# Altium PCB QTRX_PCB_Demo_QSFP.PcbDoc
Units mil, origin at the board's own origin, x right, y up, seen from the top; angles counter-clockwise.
Board outline 1267.75 x 649.64 mil, 6 copper layers (Top Layer, GND1, VCC(2V5), signal_VCC1V2, GND2, Bottom Layer), stack 37.5 mil thick; 33 components, 47 nets, 149 pads, 50 vias.
Unrouted connection lines stored in the file: 63.
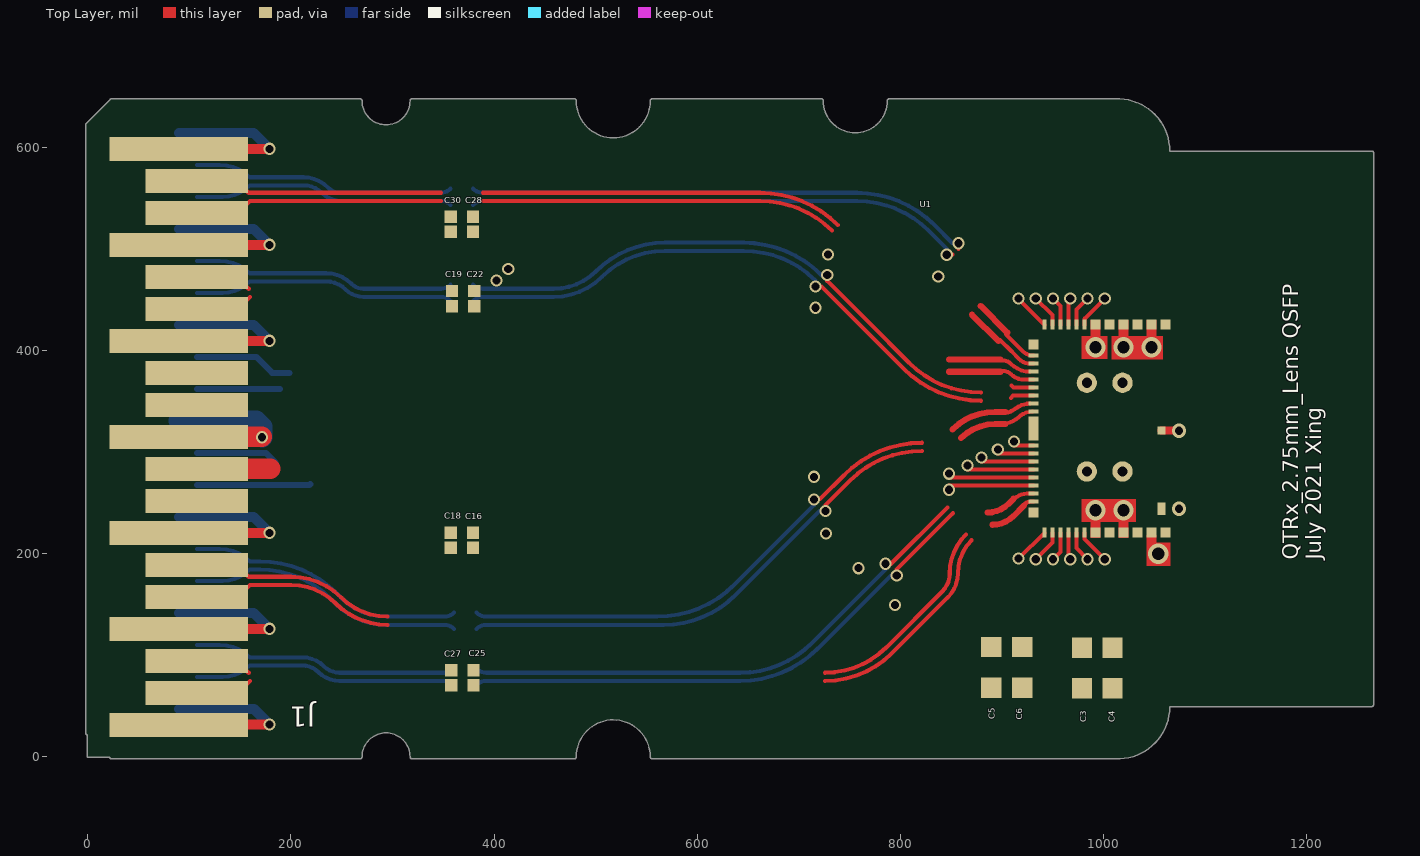
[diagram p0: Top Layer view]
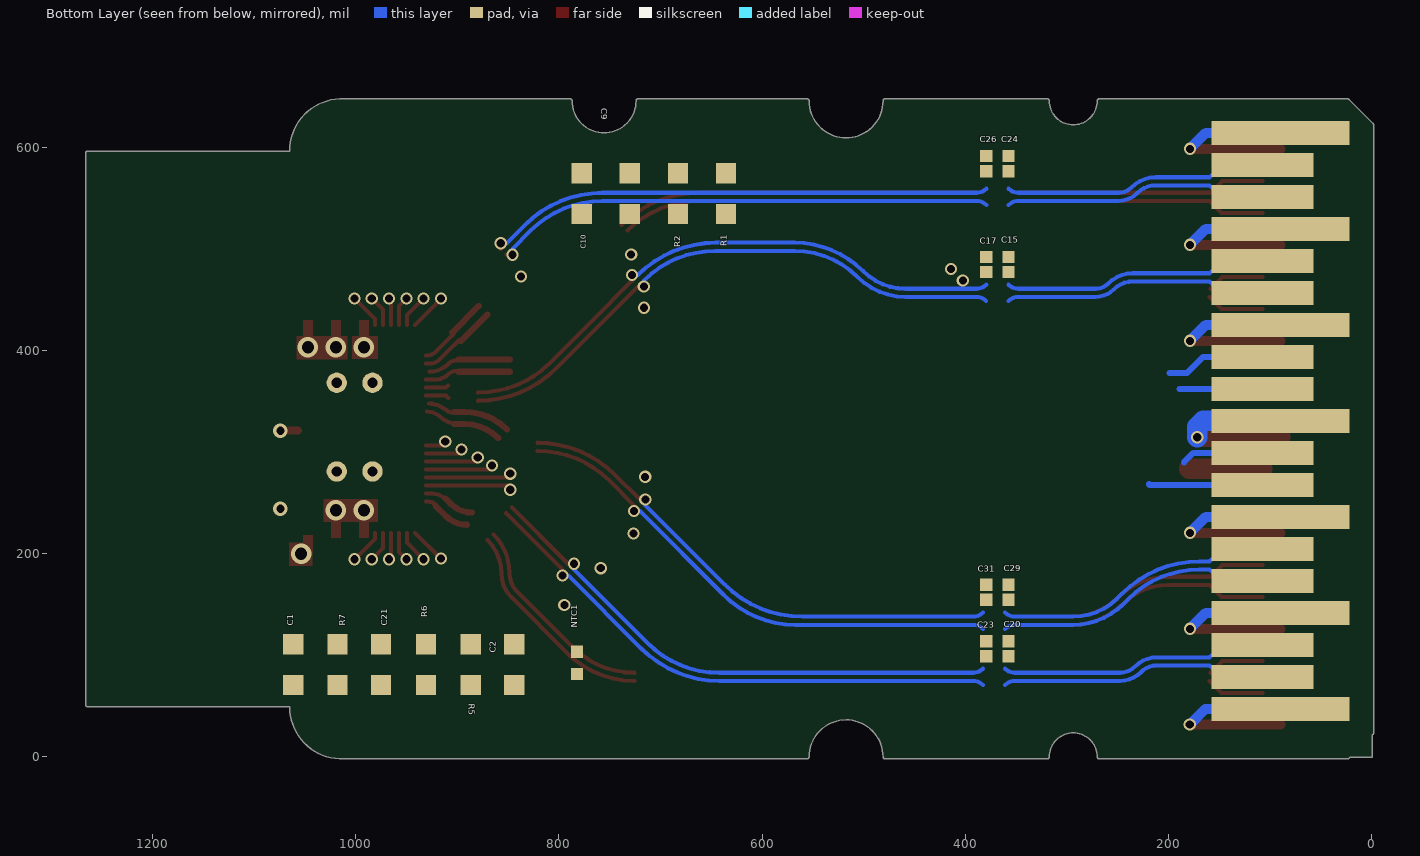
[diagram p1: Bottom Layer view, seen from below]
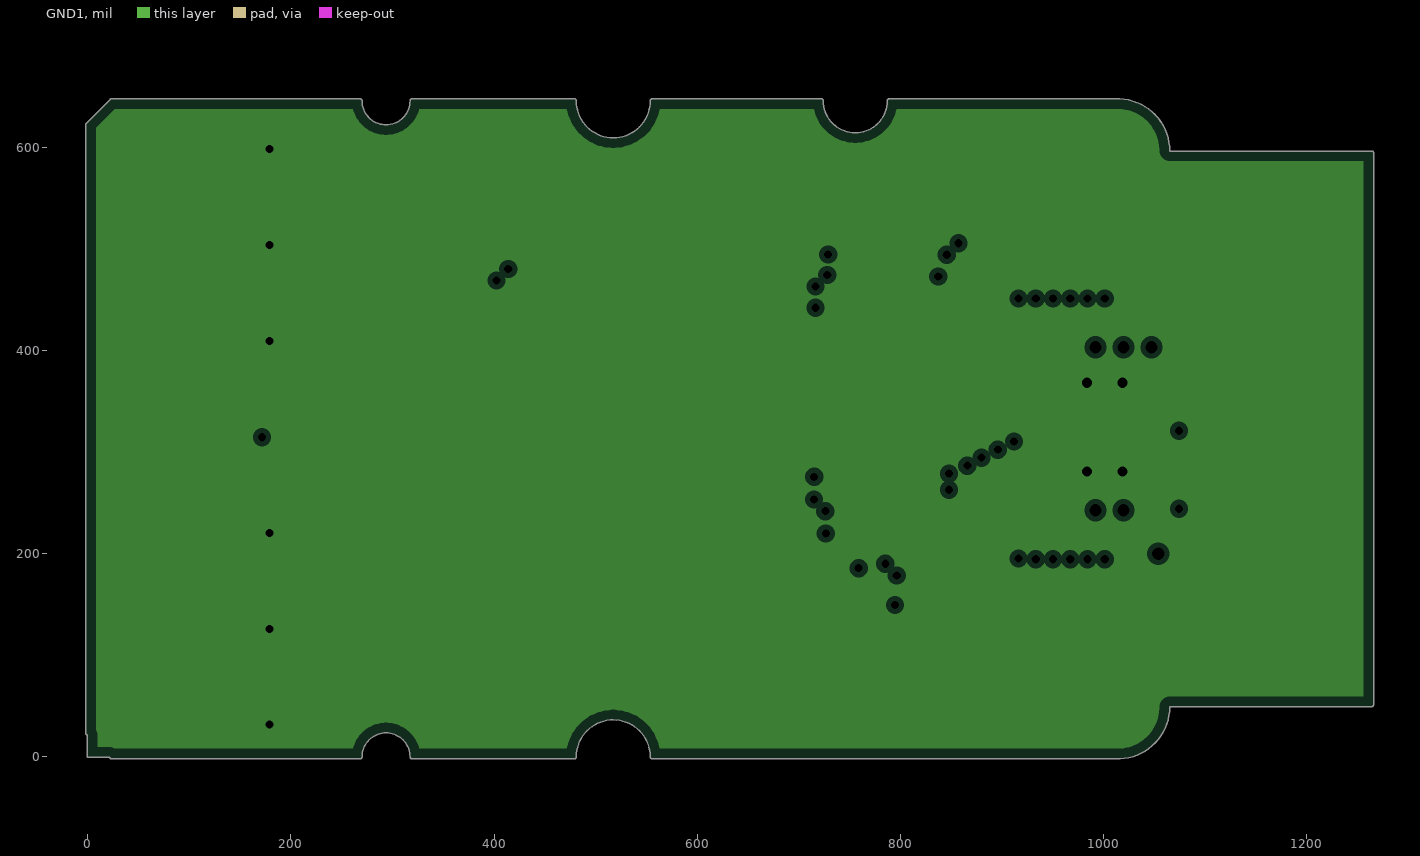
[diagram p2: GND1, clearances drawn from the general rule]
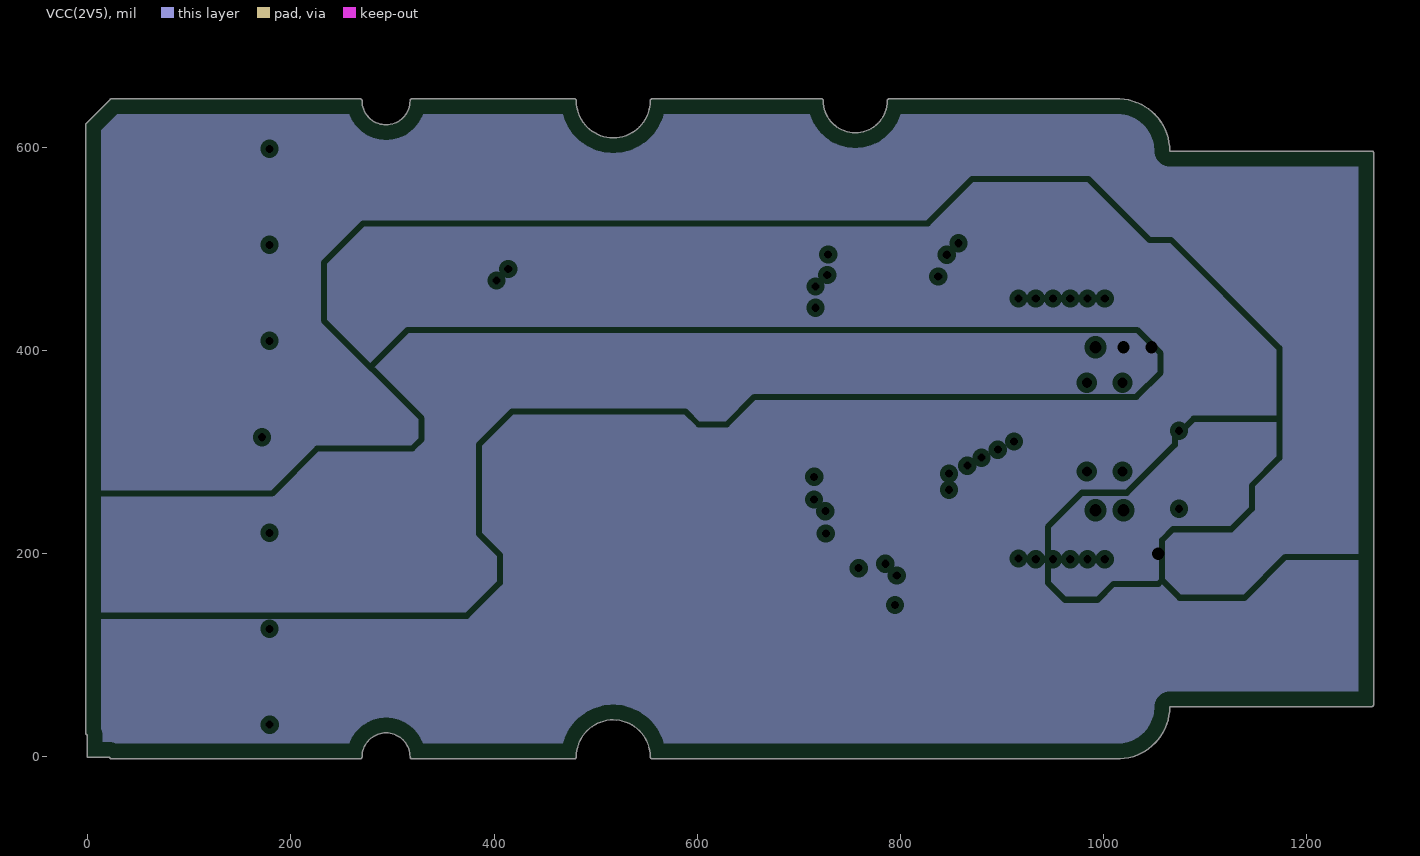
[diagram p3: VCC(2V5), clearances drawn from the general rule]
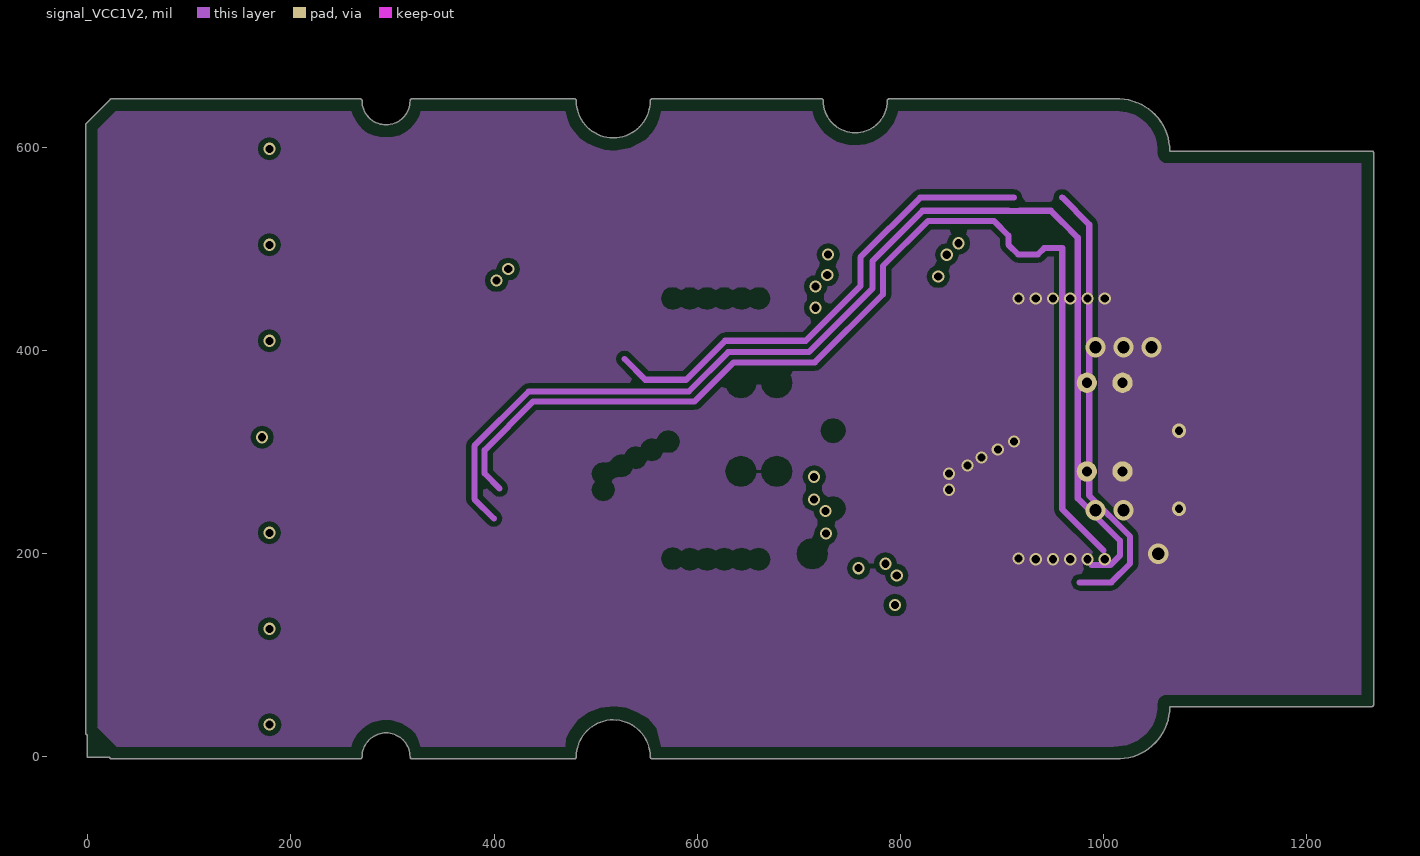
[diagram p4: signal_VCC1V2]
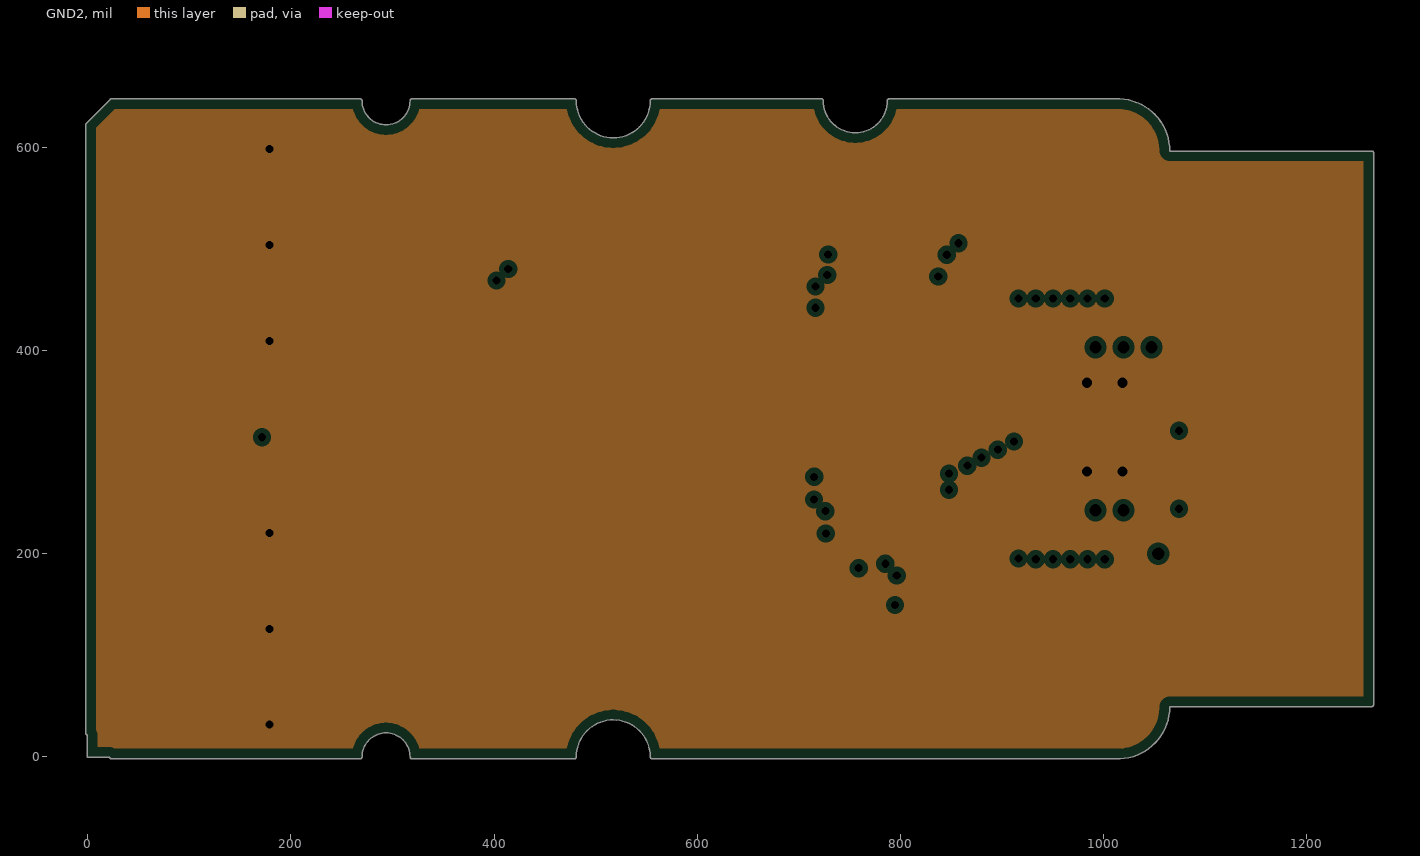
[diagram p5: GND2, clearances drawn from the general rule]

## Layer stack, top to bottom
Top Solder: solder mask 0.7, Solder Resist, Dk 3.5
Top Layer: signal copper 1.65
Dielectric 1: core 4, CORE NPG 186, Dk 4.6
GND1: plane copper 0.6, net GND
Dielectric 2: prepreg 8.3, PREPREG 7628HR, Dk 4.1
VCC(2V5): plane copper 1.2, net VCC2V5
Dielectric 3: dielectric 6, FR-4, Dk 4.8
signal_VCC1V2: signal copper 1.2
Dielectric 4: prepreg 8.3, PREPREG 7628HR, Dk 4.1
GND2: plane copper 0.6, net GND
Dielectric 5: core 4, CORE NPG 186, Dk 4.6
Bottom Layer: signal copper 1.65
Bottom Solder: solder mask 0.7, Solder Resist, Dk 3.5

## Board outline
0,-0.41 21.23,-0.41 22.22,-1.4 22.2,-1.39 ccw(c23.62,0) 23.62,-1.98 267.98,-1.98 ccw(c268.11,0) 270.08,-0.19 ccw(c268.11,0) 270.09,0 ccw(c268.11,0) 270.09,0.04 cw(c293.7,0) 317.31,0 cw(c293.7,0) 317.31,0 ccw(c319.29,0) 319.39,-1.98 478.81,-1.98 ccw(c478.94,0) 480.91,-0.19 ccw(c478.94,0) 480.92,0 ccw(c478.94,0) 480.92,0.04 cw(c517.32,0) 553.73,0 ccw(c555.71,0) 555.71,-1.99 1015.75,-1.99 ccw(c1015.75,0) 1015.96,-1.98 ccw(c1013.68,49.31) 1065.02,49.31 ccw(c1013.68,49.31) 1065.02,49.39 1263.78,49.39 ccw(c1263.78,51.38) 1265.76,51.38 1265.76,594.29 ccw(c1263.78,594.29) 1263.78,596.27 1065.02,596.27 ccw(c1013.68,596.36) 1065.02,596.36 ccw(c1013.68,596.36) 1015.83,647.65 ccw(c1015.75,645.67) 1015.75,647.65 788.98,647.65 ccw(c788.98,645.67) 786.99,645.67 cw(c755.51,645.67) 724.03,645.63 ccw(c722.05,645.67) 724.03,645.67 ccw(c722.05,645.67) 724.02,645.86 ccw(c722.05,645.67) 721.92,647.65 555.78,647.65 ccw(c555.71,645.67) 553.73,645.67 cw(c517.32,645.67) 553.73,645.67 cw(c517.32,645.67) 480.92,645.63 cw(c517.32,645.67) 480.92,645.67 ccw(c478.94,645.67) 480.91,645.86 ccw(c478.94,645.67) 478.81,647.65 319.39,647.65 ccw(c319.29,645.67) 317.31,645.67 cw(c293.7,645.67) 317.31,645.67 cw(c293.7,645.67) 270.09,645.63 cw(c293.7,645.67) 270.09,645.67 ccw(c268.11,645.67) 270.08,645.86 ccw(c268.11,645.67) 267.98,647.65 23.62,647.65 ccw(c23.62,645.67) 22.21,647.06 22.22,647.07 -1.4,623.45 -1.39,623.46 ccw(c0,622.04) -1.98,622.04 -1.98,23.62 ccw(c0,23.62) -1.39,22.21 -1.4,22.22 -0.41,21.23 -0.41,0 ccw(c0,0)

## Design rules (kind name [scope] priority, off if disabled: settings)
Clearance Clearance_1 [InPolygon and InNet('GND') vs InAnyDifferentialPair] p1: gap=10 ignorepadtopadclearanceinfootprint=TRUE
Clearance Clearance_2 [InPolygon and InNet('GND') vs InNet('DIS') or InNet('RSTN') or InNet('SCL') or InNet('SDA') or InNet('A5_1') or InNet('A5_2') or InNet('A6_1') or InNet('A6_2')] p2: gap=5.2 ignorepadtopadclearanceinfootprint=TRUE
Clearance [All] p3: gap=5 ignorepadtopadclearanceinfootprint=TRUE
DiffPairsRouting [All] p1: maxlimit=7 minlimit=7 mostfreqgap=7 toplayer_minwidth=5 toplayer_maxwidth=5 toplayer_prefwidth=5 midlayer1_minwidth=5 midlayer1_maxwidth=5 midlayer1_prefwidth=5 bottomlayer_minwidth=5 bottomlayer_maxwidth=5 bottomlayer_prefwidth=5 maxuncoupledlength=500
HoleSize [All] p1: absolutevalues=TRUE maxlimit=120 minlimit=1 maxpercent=80.000 minpercent=20.000
HoleToHoleClearance [All] p1: gap=5 allowstackedmicrovias=TRUE
PlaneClearance [All] p1: clearance=5
PlaneConnect [All] p1: planeconnectstyle=Direct reliefexpansion=30 reliefentries=4 reliefconductorwidth=30 reliefairgap=5
PolygonConnect [All] p1: connectstyle=Direct reliefconductorwidth=10 reliefentries=4 polygonreliefangle="90 Angle" airgapwidth=10
RoutingVias [All] p1: holewidth=28 width=50 viastyle="Through Hole" minholewidth=28 minwidth=50 maxholewidth=28 maxwidth=50
SilkToSilkClearance [All] p1: silktosilkclearance=5
SilkToSolderMaskClearance [IsPad] p1: minsilkscreentomaskgap=5 clearancetoexposedcopper=TRUE
SolderMaskExpansion [All] p1: expansion=4 istentingtop=FALSE
Width [All] p1: maxlimit=5 minlimit=5 preferedwidth=5
23 further rules are at their usual default settings.

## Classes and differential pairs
differential pair RX4: +RX4_p -RX4_n
differential pair RX3: +RX3_p -RX3_n
differential pair RX2: +RX2_p -RX2_n
differential pair TX4: +TX4_p -TX4_n
differential pair TX3: +TX3_p -TX3_n
differential pair TX2: +TX2_p -TX2_n
differential pair TX1: +TX1_p -TX1_n
differential pair RX1: +RX1_p -RX1_n
differential pair TXc4: +TXc4_p -TXc4_n
differential pair TXc3: +TXc3_p -TXc3_n
differential pair TXc2: +TXc2_p -TXc2_n
differential pair TXc1: +TXc1_p -TXc1_n
differential pair RXc4: +RXc4_p -RXc4_n
differential pair RXc3: +RXc3_p -RXc3_n
differential pair RXc2: +RXc2_p -RXc2_n
differential pair RXc1: +RXc1_p -RXc1_n

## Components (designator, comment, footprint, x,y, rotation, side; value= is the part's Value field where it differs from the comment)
C1 "Cap 0.1uF" 0402-eagle 1061.27,110.73 r270 bottom value=0.1uF
C2 "Cap 1nF" 0402-eagle 843.98,110.73 r270 bottom value=1nF
C3 "Cap 0.1uF" 0402-eagle 978.71,67.46 r90 top value=0.1uF
C4 "Cap 1nF" 0402-eagle 1008.71,67.46 r90 top value=1nF
C5 "Cap 0.1uF" 0402-eagle 889.41,68.03 r90 top value=0.1uF
C6 "Cap 1nF" 0402-eagle 919.8,68.03 r90 top value=1nF
C9 "Cap 0.1uF" 0402-eagle 730.14,534.36 r90 bottom value=0.1uF
C10 "Cap 1nF" 0402-eagle 777.47,534.36 r90 bottom value=1nF
C15 "Cap 0.1uF" 0201-EAGLE 379.3,477.07 r180 bottom value=0.1uF
C16 "Cap 0.1uF" 0201-EAGLE 357.3,205.72 r0 top value=0.1uF
C17 "Cap 0.1uF" 0201-EAGLE 379.3,491.88 r180 bottom value=0.1uF
C18 "Cap 0.1uF" 0201-EAGLE 357.3,220.53 r0 top value=0.1uF
C19 "Cap 0.1uF" 0201-EAGLE 358.47,443.55 r0 top value=0.1uF
C20 "Cap 0.1uF" 0201-EAGLE 357.3,98.92 r0 bottom value=0.1uF
C21 "Cap semi 10 uF" 0402-eagle 975.03,70.73 r90 bottom value=10uF
C22 "Cap 0.1uF" 0201-EAGLE 358.47,458.35 r0 top value=0.1uF
C23 "Cap 0.1uF" 0201-EAGLE 357.3,113.73 r0 bottom value=0.1uF
C24 "Cap 0.1uF" 0201-EAGLE 379.3,576.42 r180 bottom value=0.1uF
C25 "Cap 0.1uF" 0201-EAGLE 379.78,70.5 r180 top value=0.1uF
C26 "Cap 0.1uF" 0201-EAGLE 379.3,591.23 r180 bottom value=0.1uF
C27 "Cap 0.1uF" 0201-EAGLE 379.78,85.3 r180 top value=0.1uF
C28 "Cap 0.1uF" 0201-EAGLE 357.3,516.73 r0 top value=0.1uF
C29 "Cap 0.1uF" 0201-EAGLE 357.3,154.53 r0 bottom value=0.1uF
C30 "Cap 0.1uF" 0201-EAGLE 357.3,531.54 r0 top value=0.1uF
C31 "Cap 0.1uF" 0201-EAGLE 357.3,169.34 r0 bottom value=0.1uF
J1 "QSFP goldfinger" "QSFP GOLDFINGER" 89.76,31.5 r90 top
NTC1 "1k Thermistor" 0201-RES 782.09,103.42 r270 bottom value=1k
R1 "Res 0 Ohm" 0402-eagle_Res 635.47,534.36 r90 bottom value=0
R2 "Res 0 Ohm,DNI" 0402-eagle_Res 682.8,574.36 r270 bottom value="0, DNI"
R5 "Res 10k" 0402-eagle_Res 886.6,70.73 r90 bottom value=10k
R6 "Res 0 Ohm,DNI" 0402-eagle_Res 930.78,110.73 r270 bottom value="0, DNI"
R7 "Res 0 Ohm" 0402-eagle_Res 1017.84,110.73 r270 bottom value=0
U1 "QLDD_QTIA" QTRX_2P75LENS_V2 959.45,239.32 r0 top

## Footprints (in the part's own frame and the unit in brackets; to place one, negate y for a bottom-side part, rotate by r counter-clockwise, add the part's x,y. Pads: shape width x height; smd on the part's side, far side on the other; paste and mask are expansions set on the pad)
0201-EAGLE [mil]
  rect 12x12 smd: 1(0,0) 2(22,0)
  body extent -1,-6 23,6, height 12
0201-RES [mil]
  rect 12x12 smd: 1(0,0) 2(22,0)
  body extent 0,-6 23,6, height 9
0402-eagle [mil]
  rect 20x20 smd: 1(0,0) 2(40,0)
  body extent 0,-10 40,10, height 20
0402-eagle_Res [mil]
  rect 20x20 smd: 1(0,0) 2(40,0)
  body extent 0,-10 40,10, height 14
"QSFP GOLDFINGER" [mm] "mated with QSFP connector 38 pins"
  rect 0.6x3.46 smd far side paste-0.3: 1(14.8,0) 4(12.4,0) 7(10,0) 10(7.6,0) 13(5.2,0) 16(2.8,0) 19(0.4,0)
  rect 0.6x2.56 smd far side paste-0.3: 2(14,-0.45) 3(13.2,-0.45) 5(11.6,-0.45) 6(10.8,-0.45) 8(9.2,-0.45) 9(8.4,-0.45) 11(6.8,-0.45) 12(6,-0.45) 14(4.4,-0.45) 15(3.6,-0.45) 17(2,-0.45) 18(1.2,-0.45)
  rect 0.6x3.46 smd paste-0.3: 20(0,0) 23(2.4,0) 26(4.8,0) 29(7.2,0) 32(9.6,0) 35(12,0) 38(14.4,0)
  rect 0.6x2.56 smd paste-0.3: 21(0.8,-0.45) 22(1.6,-0.45) 24(3.2,-0.45) 25(4,-0.45) 27(5.6,-0.45) 28(6.4,-0.45) 30(8,-0.45) 31(8.8,-0.45) 33(10.4,-0.45) 34(11.2,-0.45) 36(12.8,-0.45) 37(13.6,-0.45)
QTRX_2P75LENS_V2 [mm]
  rect 0.1x0.25 smd paste-0.254: 1(-0.45,-0.475) 2(-0.25,-0.475) 3(-0.05,-0.475) 4(0.15,-0.475) 5(0.35,-0.475) 6(0.55,-0.475) 19(0.55,4.725) 20(0.35,4.725) 21(0.15,4.725) 22(-0.05,4.725) 23(-0.25,4.725) 24(-0.45,4.725)
  rect 0.25x0.25 smd paste-0.254: 7(0.825,-0.475) 8(1.175,-0.475) 9(1.525,-0.475) 10(1.875,-0.475) 11(2.225,-0.475) 12(2.575,-0.475) 13(2.575,4.725) 14(2.225,4.725) 15(1.875,4.725) 16(1.525,4.725) 17(1.175,4.725) 18(0.825,4.725) 25(-0.725,4.225) 43(-0.725,0.025)
  round 0.508 hole 0.254 paste+0 mask+0.102: 8(0.61,1.056) 8(0.61,3.272) 8(1.502,1.056) 8(1.502,3.272)
  rect 0.25x0.1 smd paste-0.254: 26(-0.725,3.95) 27(-0.725,3.75) 28(-0.725,3.55) 29(-0.725,3.35) 30(-0.725,3.15) 31(-0.725,2.95) 32(-0.725,2.75) 33(-0.725,2.55) 35(-0.725,1.7) 36(-0.725,1.5) 37(-0.725,1.3) 38(-0.725,1.1) 39(-0.725,0.9) 40(-0.725,0.7) 41(-0.725,0.5) 42(-0.725,0.3)
  rect 0.25x0.6 smd paste-0.254: 34(-0.725,2.125)
  rect 0.2x0.305 smd paste-0.254: 44(2.475,0.125)
  rect 0.2x0.2 smd paste-0.254: 45(2.475,2.075)
  body extent -3.89,-2.62 34.15,6.88, height 3

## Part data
C1 C2 C3 C4 C5 C6 C9 C10 C15 C16 C17 C18 C19 C20 C21 C22 C23 C24 C25 C26 C27 C28 C29 C30 C31: library part Cap, "Capacitor"
NTC1: library part Res3, "Murata NCP03XM102E05RL"
R1 R7: library part Res3_2, "Resistor"
R2 R6: library part Res3_3, "Resistor"
R5: library part Res3, "Resistor"

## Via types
v1: diameter 12, hole 8, Top Layer to Bottom Layer, tented both sides, 42 vias
v2: diameter 20, hole 12, Top Layer to Bottom Layer, tented top, 4 vias
v3: diameter 14, hole 8, Top Layer to Bottom Layer, tented both sides, 2 vias
v4: diameter 20, hole 12, Top Layer to Bottom Layer, tented both sides, 2 vias

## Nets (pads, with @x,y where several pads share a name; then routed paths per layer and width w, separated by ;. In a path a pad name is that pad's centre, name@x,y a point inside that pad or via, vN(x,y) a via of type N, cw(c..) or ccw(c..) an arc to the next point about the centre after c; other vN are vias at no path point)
A5_1: R2.2 U1.20 | length 30.5
  Top Layer w4: U1.20@973.21,425.19 973.21,440.3 v1(984.1,451.19)
A5_2: R7.1 U1.5 | length 30.5
  Top Layer w4: U1.5@973.21,220.46 973.21,205.35 v1(984.1,194.46)
A6_1: R1.1 U1.19 | length 34.3
  Top Layer w4: U1.19@981.09,425.19 981.09,431.17 v1(1001.1,451.19)
A6_2: R6.1 U1.6 | length 34.3
  Top Layer w4: U1.6@981.09,220.46 981.09,214.48 v1(1001.1,194.46)
DIS: J1.8 U1.24 | length 36.6
  Top Layer w4: v1(916.1,451.19) 916.1,450.8 U1.24@941.72,425.19
GND: C1.1 C2.1 C3.1 C4.1 C5.1 C6.1 C9.1 C10.1 C21.2 J1.1 J1.4 J1.7 J1.13 J1.16 J1.19 J1.20 J1.23 J1.26 J1.27 J1.32 J1.35 J1.38 NTC1.2 U1.8 U1.10 U1.12 U1.13 U1.15 U1.17 U1.25 U1.34 U1.43 | length 1109.1
  Top Layer w10: J1.23 v1(178.9,125.98) ; J1.26 v1(178.9,220.47) ; J1.32 v1(178.9,409.45) ; J1.35 v1(178.9,503.94) ; J1.38 v1(178.9,598.43) ; J1.20@89.96,31.69 v1(179.09,31.69)
  Bottom Layer w10: J1.19 163.54,47.24 v1(179.09,31.69) v1@178.9,31.5 ; J1.16 163.15,141.73 v1(178.9,125.98) ; J1.13 163.15,236.22 v1(178.9,220.47) ; J1.7 163.15,425.2 v1(178.9,409.45) ; J1.4 163.15,519.69 v1(178.9,503.94) ; J1.1 163.15,614.17 v1(178.9,598.43)
HV: C3.2 C4.2 U1.45 | length 17.3
  Top Layer w7.87: U1.45 v3(1074.15,321.02)
PDC1: U1.44
  other v3: 1074.15,244.24
RSSI: J1.28 U1.4 | length 99
  Top Layer w4: U1.4@965.34,220.46 965.34,196.23 v1(967.1,194.46)
  Top Layer w20: J1.28 179.72,283.46
RSTN: C21.1 J1.9 R5.2 U1.1 U1.23 | length 68.9
  Top Layer w4: v1@916.24,194.99 U1.1@941.72,220.46 ; v1(933.1,451.19) 949.59,434.7 U1.23@949.59,425.19
  other v1: 916.1,195.13
RX1_n: C16.1 J1.18
RX1_p: C18.1 J1.17
RX2_n: C20.1 J1.21
RX2_p: C23.1 J1.22
RX3_n: C25.1 J1.15
RX3_p: C27.1 J1.14
RX4_n: C29.1 J1.24
RX4_p: C31.1 J1.25
RXc1_n: C16.2 U1.42 | length 48.8
  Top Layer w4: 921.54,247.23 921.54,248.27 cw(c928.44,241.37) 928.44,251.13 U1.42
  Top Layer w6: 890.48,228.4 ccw(c890.48,257.92) 911.36,237.05 921.54,247.23
RXc1_p: C18.2 U1.41 | length 51.1
  Top Layer w3.94: 924.37,259.01 U1.41
  Top Layer w4: 911.42,254.08 912.46,254.08 cw(c924.37,242.17) 924.37,259.01
  Top Layer w6: 885.51,240.4 ccw(c885.51,269.92) 906.39,249.05 911.42,254.08
RXc2_n: C20.2 U1.40 | length 289.5
  Top Layer w4: v1@847.84,266.88 U1.40 ; 889.62,266.88 U1.40 ; 889.62,266.88 U1.40 ; 889.62,266.88 U1.40 ; 889.62,266.88 U1.40 ; 889.62,266.88 U1.40
  other v1: 847.84,262.92
RXc2_p: C23.2 U1.39 | length 83.1
  Top Layer w4: v1@847.84,274.76 U1.39
  other v1: 847.84,278.72
RXc3_n: C25.2 U1.38 | length 65.1
  Top Layer w4: v1@865.84,282.63 U1.38
  other v1: 865.84,286.63
RXc3_p: C27.2 U1.37 | length 51.1
  Top Layer w4: v1@879.84,290.5 U1.37
  other v1: 879.84,294.5
RXc4_n: C29.2 U1.36 | length 34.9
  Top Layer w4: v1@895.92,298.38 905.87,298.38 ; 905.91,298.38 U1.36
  other v1: 895.84,302.38
RXc4_p: C31.2 U1.35 | length 19.5
  Top Layer w4: v1@911.37,306.25 U1.35
  other v1: 911.84,310.28
SCL: J1.11 U1.2 U1.22 | length 224.9
  Top Layer w4: v1(933.1,194.46) 949.59,210.95 U1.2@949.59,220.46 ; v1(950.1,451.19) 957.47,443.83 U1.22@957.47,425.19
  Bottom Layer w6: J1.11 175.39,299.21 184.8,289.8 ; 107.48,362.2 189.29,362.2
SDA: J1.12 U1.3 U1.21 | length 265.5
  Top Layer w4: v1(950.1,194.46) 957.47,201.83 U1.3@957.47,220.46 ; U1.21@965.34,425.19 965.34,449.43 v1(967.1,451.19)
  Bottom Layer w6: J1.12 218.5,267.72 219.06,268.27 ; 107.48,393.7 165.91,393.7 181.65,377.95 198.86,377.95
TH: J1.31 NTC1.1
TX1_n: C15.1 J1.37 | length 302.2
  Top Layer w4: 107.48,62.99 147.99,62.99 159.74,74.74 ; J1.37 146.81,566.93 158.56,555.18 347.72,555.18
TX1_p: C17.1 J1.36 | length 301
  Top Layer w4: 107.48,94.49 146.81,94.49 158.56,82.74 ; J1.36 147.99,535.43 159.74,547.18 347.72,547.18
TX2_n: C19.1 J1.2 | length 519.7
  Bottom Layer w4: 107.48,78.74 132.52,78.74 ccw(c132.52,117.05) 159.61,89.96 211.16,89.96 cw(c211.16,67.42) 227.1,83.36 ccw(c247.91,104.17) 247.91,74.74 351.09,74.74 cw(c351.09,61.13) 360.71,70.75 ; J1.2 129.97,582.68 cw(c129.97,540.77) 159.61,570.4 ; 159.61,570.48 212.24,570.48 cw(c212.24,536.18) 236.5,560.43 ccw(c249.18,573.11) 249.18,555.18 347.64,555.18 ; 357.26,559.17 cw(c347.64,568.79) 347.72,555.18 ; 347.64,555.18 ccw(c347.64,568.79) 347.72,555.18 ; 347.64,555.18 347.72,555.18
TX2_p: C22.1 J1.3 | length 519.6
  Bottom Layer w4: 107.48,110.24 129.97,110.24 cw(c129.97,68.32) 159.61,97.96 211.16,97.96 cw(c211.16,67.42) 232.76,89.02 ccw(c247.91,104.17) 247.91,82.74 351.05,82.74 ccw(c351.05,96.35) 360.67,86.73 ; J1.3 132.52,551.18 ccw(c132.52,589.49) 159.61,562.4 ; 159.61,562.48 212.24,562.48 cw(c212.24,536.18) 230.84,554.78 ccw(c249.17,573.11) 249.17,547.18 347.72,547.18 ; 347.68,547.17 cw(c347.68,533.56) 357.3,543.18
TX3_n: C24.1 J1.34 | length 258.9
  Top Layer w4: 107.48,157.48 147.99,157.48 159.74,169.23 200.27,169.23 cw(c200.27,107.48) 243.94,151.14 ccw(c295.05,202.26) 295.05,129.97 ; J1.34 146.81,472.44 158.56,460.69
TX3_p: C26.1 J1.33 | length 260
  Top Layer w4: 107.48,188.98 146.81,188.98 158.56,177.23 200.27,177.23 cw(c200.27,107.48) 249.59,156.8 ccw(c295.02,202.22) 295.02,137.98 ; J1.33 147.99,440.94 159.74,452.69
TX4_n: C28.1 J1.5 | length 530.9
  Bottom Layer w4: 107.48,173.23 132.52,173.23 ccw(c132.52,211.54) 159.61,184.45 159.65,184.41 169.49,184.41 cw(c169.49,85.6) 239.36,155.47 244.34,150.49 ccw(c293.98,200.14) 293.98,129.93 351.09,129.93 cw(c351.09,116.32) 360.71,125.94 ; J1.5 129.97,488.19 cw(c129.97,446.28) 159.61,475.91 ; 159.61,475.95 234.8,475.95 cw(c234.8,440.98) 259.53,465.71 ccw(c271.64,477.82) 271.64,460.69 347.72,460.69 ccw(c347.72,474.3) 357.34,464.68
TX4_p: C30.1 J1.6 | length 530.8
  Bottom Layer w4: 107.48,204.72 129.97,204.72 cw(c129.97,162.81) 159.61,192.45 159.65,192.41 169.51,192.41 cw(c169.51,85.65) 245,161.14 249.99,156.15 ccw(c293.94,200.1) 293.94,137.94 351.05,137.94 ccw(c351.05,151.55) 360.67,141.93 ; J1.6 132.52,456.69 ccw(c132.52,495) 159.61,467.91 ; 159.61,467.95 234.8,467.95 cw(c234.8,440.98) 253.87,460.05 ccw(c271.64,477.82) 271.64,452.69 347.72,452.69 ; 347.76,452.68 cw(c347.76,439.07) 357.38,448.69
TXc1_n: C15.2 U1.33 | length 78.3
  Top Layer w4: 903.27,327.53 904.02,328.28 ccw(c899.67,352.9) 916.99,334.87 ; 916.1,334.06 cw(c929.76,320.4) U1.33@929.76,339.72
  Top Layer w6: 859.65,313.7 cw(c893.04,280.31) 893.04,327.53 903.27,327.53
TXc1_p: C17.2 U1.32 | length 83.4
  Top Layer w4: 903.33,339.53 904.08,338.78 ccw(c904.02,348.78) 909.02,340.12 916.5,344.83 cw(c927.06,326.53) U1.32@927.56,347.65
  Top Layer w6: 851.16,322.19 cw(c893.04,280.31) 893.04,339.53 903.33,339.53
TXc2_n: C19.2 U1.31 | length 22.9
  Top Layer w4: 908.88,353.4 910.94,355.46 U1.31
TXc2_p: C22.2 U1.30 | length 22.6
  Top Layer w4: 909.18,365.4 911.25,363.34 U1.30
TXc3_n: C24.2 U1.29 | length 83.1
  Top Layer w4: 900.71,379.96 cw(c900.71,368.66) 908.54,376.81 ; 908.58,376.77 ccw(c922,390.2) 922,371.21 ; 922.04,371.21 U1.29
  Top Layer w6: 847.93,379.06 898.59,379.06
TXc3_p: C26.2 U1.28 | length 80.6
  Top Layer w4: 900.52,390.27 cw(c900.52,378.97) 908.51,386.96 ccw(c927.52,405.97) U1.28@927.52,379.09
  Top Layer w6: 847.93,391.06 898.59,391.06
TXc4_n: C28.2 U1.27 | length 82.1
  Top Layer w3.94: 909.54,398.79 916.85,391.48 ccw(c927.76,402.4) U1.27@927.76,386.96 ; U1.27@927.76,386.96 U1.27 U1.27@927.76,386.96
  Top Layer w4: 898.04,410.29 909.54,398.79
  Top Layer w6: 870.38,435.33 896.58,409.13
TXc4_p: C30.2 U1.26 | length 72.2
  Top Layer w3.94: 908.51,411.26 920.73,399.04 ccw(c930.91,409.23) U1.26
  Top Layer w4: 903.8,415.91 908.44,411.26
  Top Layer w6: 878.87,443.82 905.07,417.62
VCC1V2: C1.2 C2.2 J1.29 J1.30 R1.2 R2.1 R5.1 R6.2 R7.2 U1.7 U1.9 U1.18
  other v2: 991.91,242.63 991.91,403.13
  other v4: 1019.47,242.63
VCC2V5: C5.2 C6.2 C9.2 C10.2 J1.10 U1.11 U1.14 U1.16
  other v2: 1053.7,199.83 1047.03,403.13
  other v4: 1019.47,403.13
copper on no net: | length 8653.9
  Top Layer w4: 388.92,547.17 661.91,547.17 cw(c661.91,447.17) 732.62,517.88 ; 388.96,555.18 661.89,555.18 cw(c661.89,447.18) 738.26,523.55 ; v1(716.37,462.96) 722.14,462.96 803.01,382.1 ccw(c879.37,458.46) 879.37,350.46 ; v1@720.76,253.61 744.68,277.53 cw(c821.05,201.16) 821.05,309.16 ; 725.67,74.73 ccw(c725.67,168.3) 791.84,102.14 846.8,157.1 ccw(c823.38,180.51) 856.5,180.51 cw(c902.97,180.51) 870.11,213.38 ; 725.71,82.75 ccw(c725.71,168.26) 786.18,107.8 841.14,162.75 ccw(c823.38,180.51) 848.5,180.51 cw(c902.97,180.51) 864.45,219.03 ; v1(726.08,241.82) v1@726.08,247.6 ; 726.46,247.99 750.34,271.87 cw(c821.05,201.16) 821.05,301.16 ; v1@727.8,468.62 767.36,429.06 808.66,387.75 ccw(c879.37,458.46) 879.37,358.46 ; v1@727.95,468.47 v1(727.95,474.22) ; v1(785.16,190.05) 790.84,190.05 846.22,245.43 ; v1(796.34,178.56) 796.34,184.24 851.87,239.77 ; v1(845.59,494.22) v1@851.37,494.22 ; v1@857.17,499.73 v1(857.17,505.48)
  Top Layer w20: 89.76,314.96 v1@171.3,314.96
  signal_VCC1V2 w6: 399.76,234.61 380.63,253.74 380.63,306.1 434.09,359.57 591.73,359.57 630.43,398.27 709.76,398.27 772.32,460.83 772.32,487.91 821.89,537.48 906.14,537.48 906.19,537.43 916.96,537.43 917.01,537.48 947.99,537.48 959.45,526.02 974.49,511.06 974.49,254.37 1015.94,212.91 1015.94,197.99 1006.63,188.68 987.97,188.68 ; 405.51,264.02 390.63,278.9 390.63,301.96 438.24,349.57 597.17,349.57 635.87,388.27 715.83,388.27 782.83,455.28 782.83,483.15 ; 528.43,391.57 548.82,371.18 589.06,371.18 627.44,409.57 706.77,409.57 707.05,409.84 707.17,409.84 760.63,463.31 760.63,491.65 819.41,550.43 911.57,550.43 ; 782.64,482.95 782.83,483.15 ; 959.05,550.71 985.87,523.89 985.87,257.13 1025.94,217.06 1025.94,190.2 1007.52,171.77 976.42,171.77 ; 999.76,203.27 959.28,243.75 959.28,500.67 941.46,500.67 935.24,494.45 915.91,494.45 906.26,504.09 906.26,513.15 892.17,527.24 826.93,527.24 782.83,483.15
  Bottom Layer w4: 379.26,559.17 ccw(c388.88,568.79) 388.88,555.18 757.04,555.18 cw(c757.04,447.18) 833.41,523.55 851.48,505.48 v1(857.17,505.48) ; 379.3,543.18 cw(c388.92,533.56) 388.92,547.17 757.06,547.17 cw(c757.06,447.17) 827.77,517.88 845.59,500.05 v1(845.59,494.22) ; 379.38,448.69 cw(c389,439.07) 389,452.68 458.65,452.68 ccw(c458.65,519.66) 506.01,472.3 cw(c568.14,410.16) 568.14,498.03 645.77,498.03 cw(c645.77,398.2) 716.37,468.79 v1(716.37,462.96) ; 379.34,464.68 ccw(c388.96,474.3) 388.96,460.69 458.69,460.69 ccw(c458.69,519.62) 500.35,477.95 cw(c568.14,410.16) 568.14,506.03 645.86,506.03 cw(c645.86,398.41) 721.96,474.51 ; 382.67,86.73 ccw(c392.29,96.35) 392.29,82.75 642.11,82.75 ccw(c642.11,182.75) 712.82,112.04 785.16,184.37 v1(785.16,190.05) ; 382.67,141.93 ccw(c392.29,151.55) 392.29,137.94 560.37,137.94 ccw(c560.37,245.94) 636.74,169.58 v1@714.65,247.48 ; 382.71,70.75 cw(c392.33,61.13) 392.33,74.73 642.1,74.73 ccw(c642.1,182.73) 718.46,106.37 790.66,178.56 v1(796.34,178.56) ; 382.71,125.94 cw(c392.33,116.32) 392.33,129.93 566.99,129.93 ccw(c566.99,229.93) 637.7,159.22 720.3,241.82 v1(726.08,241.82) ; v1@714.89,247.73 v1(714.89,253.32) ; v1@722.25,474.22 v1(727.95,474.22)
  Bottom Layer w20: 89.76,330.71 165.98,330.71 171.69,325 v1(171.69,314.61)
  other v1: 794.61,149.37 758.82,185.71 726.57,219.84 715.04,275.59 716.34,442.05 402.38,468.86 837.24,472.72 413.96,480.11 728.82,494.37

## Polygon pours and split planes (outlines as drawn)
VCC1V2 on signal_VCC1V2 "sig1Layer-GND" (solid, pour order 23): 1253.78,61.28 1060.64,61.28 1058.15,60.35 1056.13,59.01 1054.45,56.97 1053.23,54.68 1052.8,50.79 1052.8,47.05 1051.18,38.82 1048.11,30.87 1042.05,22.66 1033.03,15.79 1022.8,11.18 1010,10.04 564.76,10.04 560.31,27.91 551.57,38.15 540.98,43.94 530.83,48.11 518.37,49.67 504.61,48.11 492.87,43.94 482.49,36.42 474.43,25.49 470.59,18.31 469.88,10.04 327.91,10.04 325.47,17.56 322.69,22.66 318.3,27.05 309.09,33.03 297.72,36.42 288.98,35.87 280.35,33.98 274.68,30.87 269.65,27.05 265.51,22.66 262.01,17.56 260.39,14.02 259.45,10.04 28.43,10.04 9.49,28.98 10,29.49 10,617.91 27.76,635.67 259.45,635.63 260.39,632.56 261.73,629.45 265.16,623.39 269.65,618.43 274.68,614.49 280.79,612.05 287.13,610.32 293.43,609.88 300.54,610.32 307.52,612.05 313.48,615.1 318.7,619.17 322.91,624.53 326.22,630 327.4,632.8 327.95,635.67 469.96,635.67 471.83,628.01 474.65,621.02 478.94,615.1 484.49,608.62 491.61,604.05 499.49,600.35 508.54,597.4 518.37,596.77 534.57,599.41 549.13,607.48 555.71,614.49 560.31,621.02 563.19,629.17 564.76,635.58 713.19,635.67 713.66,633.15 714.65,630 715.5,627.28 716.89,624.84 720.87,618.82 725.16,613.74 731.1,609.13 737.28,605.35 746.24,602.93 750.91,602.17 755.83,601.89 765.98,602.93 773.46,605.35 780.12,609.13 786.46,614.49 790.67,619.68 792.92,622.46 794.41,625.63 796.5,630.43 797.52,633.15 797.83,635.67 1015.43,635.67 1022.8,634.49 1030.36,631.91 1036.02,628.54 1041.26,624.17 1045.79,618.98 1049.13,613.35 1050.59,609.88 1051.69,606.46 1052.36,602.93 1052.8,599.41 1052.95,597.52 1052.91,595.55 1052.91,593.74 1053.03,592.8 1053.23,591.85 1053.58,590.71 1054.02,589.68 1055.16,587.91 1056.65,586.42 1057.83,585.55 1059.21,584.8 1060.64,584.46 1062.4,584.25 1253.78,584.25
GND on GND1 (split plane): 182 vertices, not listed, extent 8.1,8.1 1255.68,637.57
GND on GND2 (split plane): 182 vertices, not listed, extent 8.1,8.1 1255.68,637.57
VCC2V5 on VCC(2V5) (split plane): 1169.93,295.48 1143.66,269.21 1143,268.22 1142.77,267.05 1142.77,245.48 1124.32,227.04 1068.11,227.04 1066.94,226.8 1065.95,226.14 1055.4,215.59 1054.73,214.6 1054.5,213.43 1054.5,175.24 1052.43,173.18 1009.61,173.18 1008.44,172.94 1007.44,172.28 992.83,157.67 963.08,157.67 948.1,172.64 948.1,225.07 979.89,256.86 1022.95,256.86 1024.12,257.1 1025.12,257.76 1072.32,304.96 1072.98,305.96 1073.22,307.13 1073.22,313.06 1089.89,329.74 1169.93,329.74
VCC2V5 on VCC(2V5) (split plane): 1053,395.78 1053,379.5 1030.82,357.31 656.26,357.31 655.09,357.08 654.1,356.41 627.83,330.15 602.49,330.15 590.43,342.2 589.44,342.87 588.27,343.1 417.83,343.1 416.66,342.87 415.67,342.2 382.92,309.45 382.25,308.45 382.02,307.28 382.02,219.45 382.25,218.28 382.92,217.29 402.65,197.55 402.65,172.53 372.08,141.96 13.09,141.96 13.09,256.04 181.5,256.04 182.67,256.27 183.66,256.93 227.17,300.45 319.57,300.45 320.74,300.68 321.73,301.34 330.82,310.44 331.49,311.43 331.72,312.6 331.72,333.07 331.49,334.24 330.82,335.23 282.51,383.54 316.11,417.14 1031.65,417.14
VCC2V5 on VCC(2V5) (split plane): 153 vertices, not listed, extent 13.09,159.67 1250.69,632.58
VCC2V5 on VCC(2V5) (split plane): 173 vertices, not listed, extent 13.09,13.08 1250.69,565.84

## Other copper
Top Layer:
  rectangle net VCC1V2: 986.95,402.09 996.85,430.09
  region net VCC2V5: 1052,218.53 1042.1,218.53 1042.1,200.18 1052,200.18
  region net VCC2V5: 1065.6,210.93 1042.35,210.93 1042.35,187.83 1065.6,187.83
  rectangle net VCC2V5: 1042.1,412.59 1051.95,430.09
  rectangle net VCC1V2: 977.95,391.49 1003.7,414.34
  region net VCC1V2: 996.87,243.56 986.97,243.56 986.97,215.56 996.87,215.56
  region net VCC1V2: 1024.4,233.06 1014.55,233.06 1014.55,215.56 1024.4,215.56
  rectangle net VCC2V5: 1014.5,411.94 1024.4,430.04
  region net VCC2V5: 1058.4,414.34 1007.95,414.34 1007.95,391.24 1058.4,391.24
  rectangle net VCC1V2: 977.95,230.99 1031.75,253.84
VCC(2V5) (plane layer: these items are gaps in the copper):
  lines w6: -0.2,138.9 373.35,138.9 405.71,171.26 405.71,198.82 385.08,219.45 385.08,307.28 417.83,340.04 588.27,340.04 601.22,327.09 629.09,327.09 656.26,354.25 1032.09,354.25 1056.06,378.23 1056.06,397.05 1032.91,420.2 314.84,420.2 278.15,383.5 ; 0,259.09 181.5,259.09 225.91,303.5 319.57,303.5 328.66,312.6 328.66,333.07 232.44,429.29 232.44,486.3 271.18,525.04 826.85,525.04 870.71,568.9 984.96,568.9 1045.04,508.82 1066.3,508.82 1172.99,402.13 1172.99,294.21 1145.83,267.05 1145.83,244.21 1125.59,223.98 1068.11,223.98 1057.56,213.43 1057.56,173.86 ; 1172.95,332.8 1088.62,332.8 1070.16,314.33 1070.16,307.13 1022.95,259.92 978.62,259.92 945.04,226.34 945.04,171.38 961.81,154.61 994.09,154.61 1009.61,170.12 1053.7,170.12 1057.44,173.86 1057.56,173.86 ; 1263.39,196.81 1178.86,196.81 1138.66,156.61 1074.8,156.61 1057.56,173.86

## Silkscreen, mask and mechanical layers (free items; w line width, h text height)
Top Overlay:
  text "QTRx_2.75mm_Lens QSFP / July 2021 Xing" at 1214.12,194.22 h15 r90
Top Solder:
  region: 1064.8,434.69 905.12,434.69 905.12,211.42 1064.8,211.42
Bottom Solder:
  region: 1064.76,433.74 748.86,433.74 748.86,211.42 1064.76,211.42
Mechanical 1:
  lines w0.79: 0,23.62 0,0 23.62,0
  lines w3.94: 23.62,0 268.11,0 cw(c293.7,0) 319.29,0 478.94,0 cw(c517.32,0) 555.71,0 1015.75,0 ccw(c1013.68,49.31) 1062.99,51.38 1263.78,51.38 1263.78,594.29 1062.99,594.29 ccw(c1013.68,596.36) 1015.75,645.67 788.98,645.67 cw(c755.51,645.67) 722.05,645.67 555.71,645.67 cw(c517.32,645.67) 478.94,645.67 319.29,645.67 cw(c293.7,645.67) 268.11,645.67 23.62,645.67 0,622.04 0,23.62 23.62,0 ; 23.62,0 23.62,0 ; 23.62,0 23.62,0
Mechanical 2:
  lines w1.97: 314.96,62.8 330.59,62.8 330.59,50.24 ; 314.96,62.91 314.96,582.76 ; 315.04,582.83 330.59,582.83 ; 330.71,582.91 330.71,595.47 670.67,595.47 670.67,50.2 330.83,50.2 ; 708.66,78.94 708.66,566.73 1263.78,566.73 1263.78,78.94 708.66,78.94
Mechanical 3:
  lines w1.97: 314.96,62.8 314.96,582.8 315,582.83 ; 330.59,62.76 330.59,50.2 750,50.2 750,595.47 330.71,595.47 330.71,582.87 ; 330.59,62.8 255.92,62.8 255.92,582.83 330.59,582.83
Mechanical 13:
  lines w1.97: 725,322.83 1203.46,322.83 ; 750.12,433.07 1062.99,433.07 1062.99,212.6 750.35,212.6 ; 1015.75,81.89 1015.75,560.35
Mechanical 30:
  lines w0.39: 987.6,340.2 1007.87,341.54 ; 1006.43,394.14 1019.61,402.56 ; 1006.53,398.94 1010.51,401.89 ; 1012.53,305.44 1025.25,305.44
  lines w0.79: 989.33,242.57 989.33,396.27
